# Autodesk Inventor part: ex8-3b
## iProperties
Author: Administrator
Created: 2001-03
Part Number: ex8-3b
Document SubType Name: Modeling
Designer: Administrator
Control State: 0
Master: False
Checked Out: False
PropertySet Name: Design Tracking Control
Shininess: 20.0
Length Units: 11272
Angle Units: 11286
Time Units: 11279
Mass Units: 11290
Length Display Precision: 3
Angle Display Precision: 2
Compacted: False
PropertySet Name: _Private Model Information
Density: 0.0
Volumn: 0.0
Area: 0.0
PropertySet Name: Model Information
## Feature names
1. Extrusion1
2. Hole1
